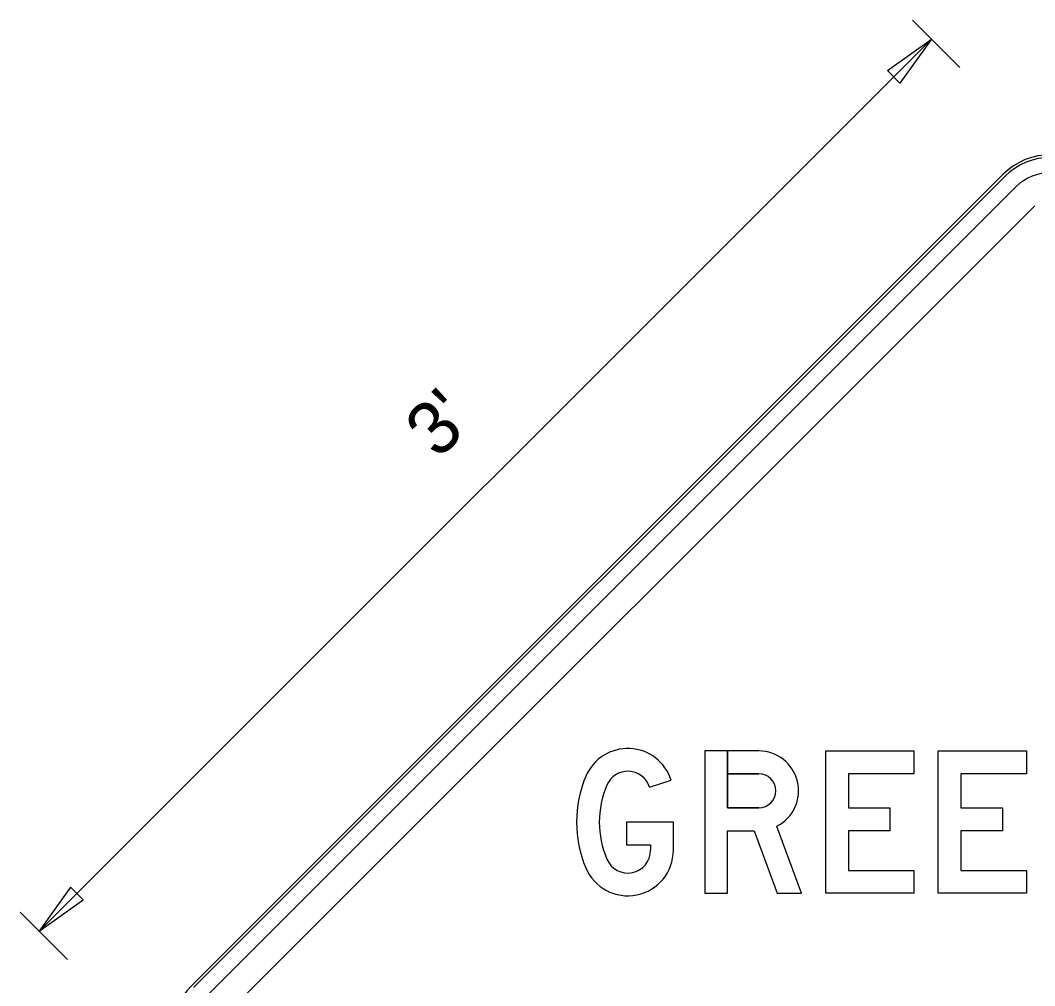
# Model space of a CAD drawing. Extents: x 1788.1 to 1851.2, y 237.2 to 283.4.
# Drawn here: x 1805.419 to 1808.268, y 277.081 to 279.794 of the extents above; entities that cross this region are included whole.
import ezdxf

# ---------------------------------------------------------------- set-up
doc = ezdxf.new("R2010")
doc.units = 0
for name, color, linetype in [('GSBWFILL', 7, 'Continuous'), ('GSCOLORFILL', 7, 'Continuous'), ('GSDIMS', 7, 'Continuous'), ('GSOUTLINE', 7, 'Continuous')]:
    doc.layers.add(name, color=color, linetype=linetype)

msp = doc.modelspace()

# ---------------------------------------------------------------- linework, layer by layer
at = {"layer": 'GSBWFILL'}
for p, q in [((1808.1797, 279.3608), (1805.8997, 277.0807)), ((1808.2153, 279.3253), (1805.9352, 277.0452)), ((1805.9882, 276.9922), (1808.2683, 279.2722)), ((1807.1862, 277.6389), (1807.2471, 277.6584))]:
    msp.add_line(p, q, dxfattribs=at)
for points in [[(1807.4931, 277.5804), (1807.4052, 277.5804), (1807.4052, 277.7404), (1807.3412, 277.7404), (1807.3412, 277.3404), (1807.4052, 277.3404), (1807.4052, 277.5164), (1807.4803, 277.5164), (1807.545, 277.3404), (1807.6132, 277.3404), (1807.544, 277.5286)], [(1807.4052, 277.7404), (1807.4052, 277.6764), (1807.4931, 277.6764)], [(1807.4931, 277.7404), (1807.4052, 277.7404)], [(1807.1212, 277.5404), (1807.1212, 277.4764), (1807.1892, 277.4764), (1807.1892, 277.4614)], [(1807.2532, 277.4614), (1807.2532, 277.5404), (1807.1212, 277.5404)]]:
    msp.add_lwpolyline(points, dxfattribs=at)
for points in [[(1807.9292, 277.6764), (1807.7452, 277.6764), (1807.7452, 277.5804), (1807.8615, 277.5804), (1807.8615, 277.5164), (1807.7452, 277.5164), (1807.7452, 277.4044), (1807.9292, 277.4044), (1807.9292, 277.3404), (1807.6812, 277.3404), (1807.6812, 277.7404), (1807.9292, 277.7404)], [(1808.2452, 277.6764), (1808.0612, 277.6764), (1808.0612, 277.5804), (1808.1775, 277.5804), (1808.1775, 277.5164), (1808.0612, 277.5164), (1808.0612, 277.4044), (1808.2452, 277.4044), (1808.2452, 277.3404), (1807.9972, 277.3404), (1807.9972, 277.7404), (1808.2452, 277.7404)]]:
    msp.add_lwpolyline(points, close=True, dxfattribs=at)
for centre, radius, start, end in [((1808.3125, 279.228), 0.1878, 45, 135), ((1808.3125, 279.228), 0.1375, 45, 135), ((1806.0324, 276.948), 0.1878, 135, 225)]:
    msp.add_arc(centre, radius, start, end, dxfattribs=at)
for centre, major_axis, start_param, end_param in [((1807.1252, 277.6194), (0, 0.128), 5.021999, 7.454324), ((1807.4931, 277.6284), (0, 0.112), 3.613317, 6.283185), ((1807.1252, 277.6194), (0, 0.064), 5.021999, 7.454324), ((1807.4931, 277.6284), (0, 0.048), 3.141593, 6.283185), ((1807.3122, 277.5404), (0, 0.331), 1.171139, 1.970454), ((1807.3122, 277.5404), (0, 0.267), 1.171139, 1.970454), ((1807.1252, 277.4614), (0, 0.128), 1.970454, 4.712389), ((1807.1252, 277.4614), (0, 0.064), 1.970454, 4.712389)]:
    msp.add_ellipse(centre, major_axis=major_axis, ratio=0.999993, start_param=start_param, end_param=end_param, dxfattribs=at)
at = {"layer": 'GSCOLORFILL'}
for p, q in [((1808.1797, 279.3608), (1805.8997, 277.0807)), ((1808.1797, 279.3608), (1805.8997, 277.0807)), ((1805.905, 277.0754), (1808.185, 279.3555)), ((1808.2153, 279.3253), (1805.9352, 277.0452)), ((1805.9882, 276.9922), (1808.2683, 279.2722)), ((1807.1862, 277.6389), (1807.2471, 277.6584))]:
    msp.add_line(p, q, dxfattribs=at)
for points in [[(1807.4931, 277.5804), (1807.4052, 277.5804), (1807.4052, 277.7404), (1807.3412, 277.7404), (1807.3412, 277.3404), (1807.4052, 277.3404), (1807.4052, 277.5164), (1807.4803, 277.5164), (1807.545, 277.3404), (1807.6132, 277.3404), (1807.544, 277.5286)], [(1807.4052, 277.7404), (1807.4052, 277.6764), (1807.4931, 277.6764)], [(1807.4931, 277.7404), (1807.4052, 277.7404)], [(1807.1212, 277.5404), (1807.1212, 277.4764), (1807.1892, 277.4764), (1807.1892, 277.4614)], [(1807.2532, 277.4614), (1807.2532, 277.5404), (1807.1212, 277.5404)]]:
    msp.add_lwpolyline(points, dxfattribs=at)
for points in [[(1807.9292, 277.6764), (1807.7452, 277.6764), (1807.7452, 277.5804), (1807.8615, 277.5804), (1807.8615, 277.5164), (1807.7452, 277.5164), (1807.7452, 277.4044), (1807.9292, 277.4044), (1807.9292, 277.3404), (1807.6812, 277.3404), (1807.6812, 277.7404), (1807.9292, 277.7404)], [(1808.2452, 277.6764), (1808.0612, 277.6764), (1808.0612, 277.5804), (1808.1775, 277.5804), (1808.1775, 277.5164), (1808.0612, 277.5164), (1808.0612, 277.4044), (1808.2452, 277.4044), (1808.2452, 277.3404), (1807.9972, 277.3404), (1807.9972, 277.7404), (1808.2452, 277.7404)]]:
    msp.add_lwpolyline(points, close=True, dxfattribs=at)
for centre, radius, start, end in [((1808.3125, 279.228), 0.1878, 45, 135), ((1808.3125, 279.228), 0.1878, 45, 135), ((1808.3125, 279.228), 0.1802, 45, 135), ((1808.3125, 279.228), 0.1375, 45, 135), ((1806.0324, 276.948), 0.1878, 135, 225), ((1806.0324, 276.948), 0.1878, 135, 225)]:
    msp.add_arc(centre, radius, start, end, dxfattribs=at)
for centre, major_axis, start_param, end_param in [((1807.1252, 277.6194), (0, 0.128), 5.021999, 7.454324), ((1807.4931, 277.6284), (0, 0.112), 3.613317, 6.283185), ((1807.1252, 277.6194), (0, 0.064), 5.021999, 7.454324), ((1807.4931, 277.6284), (0, 0.048), 3.141593, 6.283185), ((1807.3122, 277.5404), (0, 0.331), 1.171139, 1.970454), ((1807.3122, 277.5404), (0, 0.267), 1.171139, 1.970454), ((1807.1252, 277.4614), (0, 0.128), 1.970454, 4.712389), ((1807.1252, 277.4614), (0, 0.064), 1.970454, 4.712389)]:
    msp.add_ellipse(centre, major_axis=major_axis, ratio=0.999993, start_param=start_param, end_param=end_param, dxfattribs=at)
at = {"layer": 'GSDIMS'}
for p, q in [((1808.0577, 279.6611), (1807.9252, 279.7937)), ((1805.4717, 277.2341), (1807.9782, 279.7406)), ((1805.5512, 277.1546), (1805.4186, 277.2872))]:
    msp.add_line(p, q, dxfattribs=at)
for points in [[(1807.9782, 279.7406), (1807.8898, 279.6169), (1807.8544, 279.6523)], [(1805.4717, 277.2341), (1805.5954, 277.3225), (1805.5601, 277.3579)]]:
    msp.add_lwpolyline(points, close=True, dxfattribs=at)
at = {"layer": 'GSOUTLINE'}
for p, q in [((1808.1797, 279.3608), (1805.8997, 277.0807)), ((1808.2153, 279.3253), (1805.9352, 277.0452)), ((1808.2683, 279.2722), (1805.9882, 276.9922)), ((1807.1862, 277.6389), (1807.2471, 277.6584))]:
    msp.add_line(p, q, dxfattribs=at)
for points in [[(1807.4931, 277.7404), (1807.3412, 277.7404), (1807.3412, 277.3404), (1807.4052, 277.3404), (1807.4052, 277.5164), (1807.4803, 277.5164), (1807.545, 277.3404), (1807.6132, 277.3404), (1807.544, 277.5286)], [(1807.4931, 277.6764), (1807.4052, 277.6764), (1807.4052, 277.5804), (1807.4931, 277.5804)], [(1807.1212, 277.5404), (1807.1212, 277.4764), (1807.1892, 277.4764), (1807.1892, 277.4614)], [(1807.2532, 277.4614), (1807.2532, 277.5404), (1807.1212, 277.5404)]]:
    msp.add_lwpolyline(points, dxfattribs=at)
for points in [[(1807.9292, 277.6764), (1807.7452, 277.6764), (1807.7452, 277.5804), (1807.8615, 277.5804), (1807.8615, 277.5164), (1807.7452, 277.5164), (1807.7452, 277.4044), (1807.9292, 277.4044), (1807.9292, 277.3404), (1807.6812, 277.3404), (1807.6812, 277.7404), (1807.9292, 277.7404)], [(1808.2452, 277.6764), (1808.0612, 277.6764), (1808.0612, 277.5804), (1808.1775, 277.5804), (1808.1775, 277.5164), (1808.0612, 277.5164), (1808.0612, 277.4044), (1808.2452, 277.4044), (1808.2452, 277.3404), (1807.9972, 277.3404), (1807.9972, 277.7404), (1808.2452, 277.7404)]]:
    msp.add_lwpolyline(points, close=True, dxfattribs=at)
for centre, radius, start, end in [((1808.3125, 279.228), 0.1878, 45, 135), ((1808.3125, 279.228), 0.1375, 45, 135), ((1806.0324, 276.948), 0.1878, 135, 225)]:
    msp.add_arc(centre, radius, start, end, dxfattribs=at)
for centre, major_axis, start_param, end_param in [((1807.1252, 277.6194), (0, 0.128), 5.021999, 7.454324), ((1807.4931, 277.6284), (0, 0.112), 3.613317, 6.283185), ((1807.1252, 277.6194), (0, 0.064), 5.021999, 7.454324), ((1807.4931, 277.6284), (0, 0.048), 3.141593, 6.283185), ((1807.3122, 277.5404), (0, 0.331), 1.171139, 1.970454), ((1807.3122, 277.5404), (0, 0.267), 1.171139, 1.970454), ((1807.1252, 277.4614), (0, 0.128), 1.970454, 4.712389), ((1807.1252, 277.4614), (0, 0.064), 1.970454, 4.712389)]:
    msp.add_ellipse(centre, major_axis=major_axis, ratio=0.999993, start_param=start_param, end_param=end_param, dxfattribs=at)

# ---------------------------------------------------------------- texts
at = {"layer": 'GSDIMS'}
msp.add_text("3'", height=0.15, rotation=45, dxfattribs=at).set_placement((1806.593, 278.5572))

doc.saveas('drawing.dxf')
